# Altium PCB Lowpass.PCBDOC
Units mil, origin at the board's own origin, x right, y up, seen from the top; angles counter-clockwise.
Board outline 6000 x 4000 mil, 2 copper layers (Top Layer, Bottom Layer); 8 components, 7 nets, 22 pads, 0 vias.
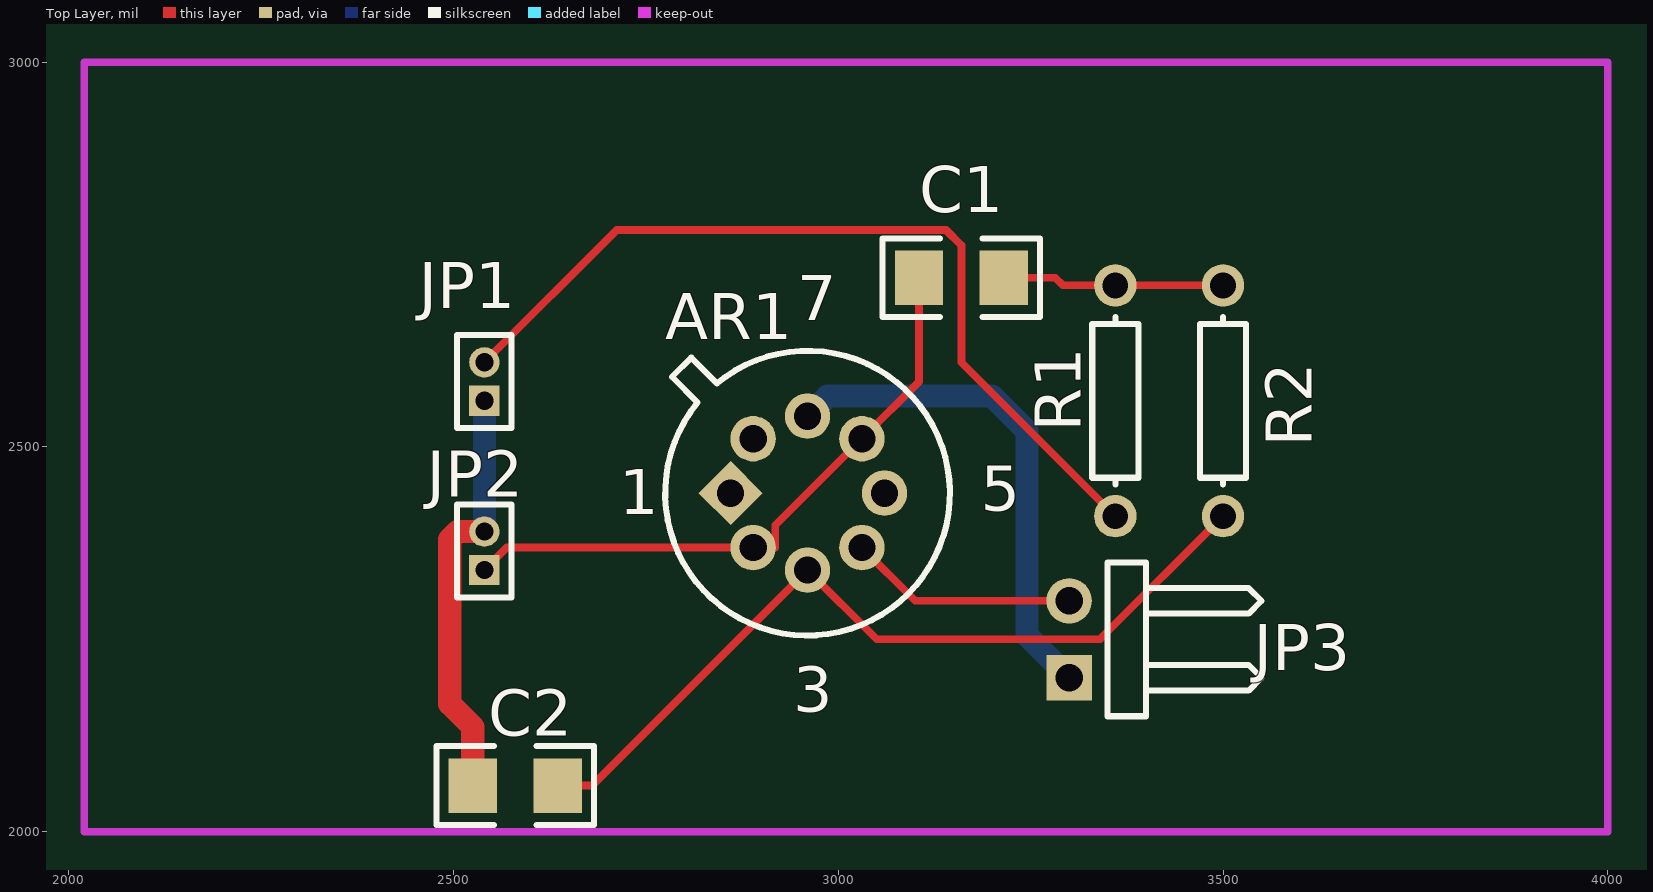
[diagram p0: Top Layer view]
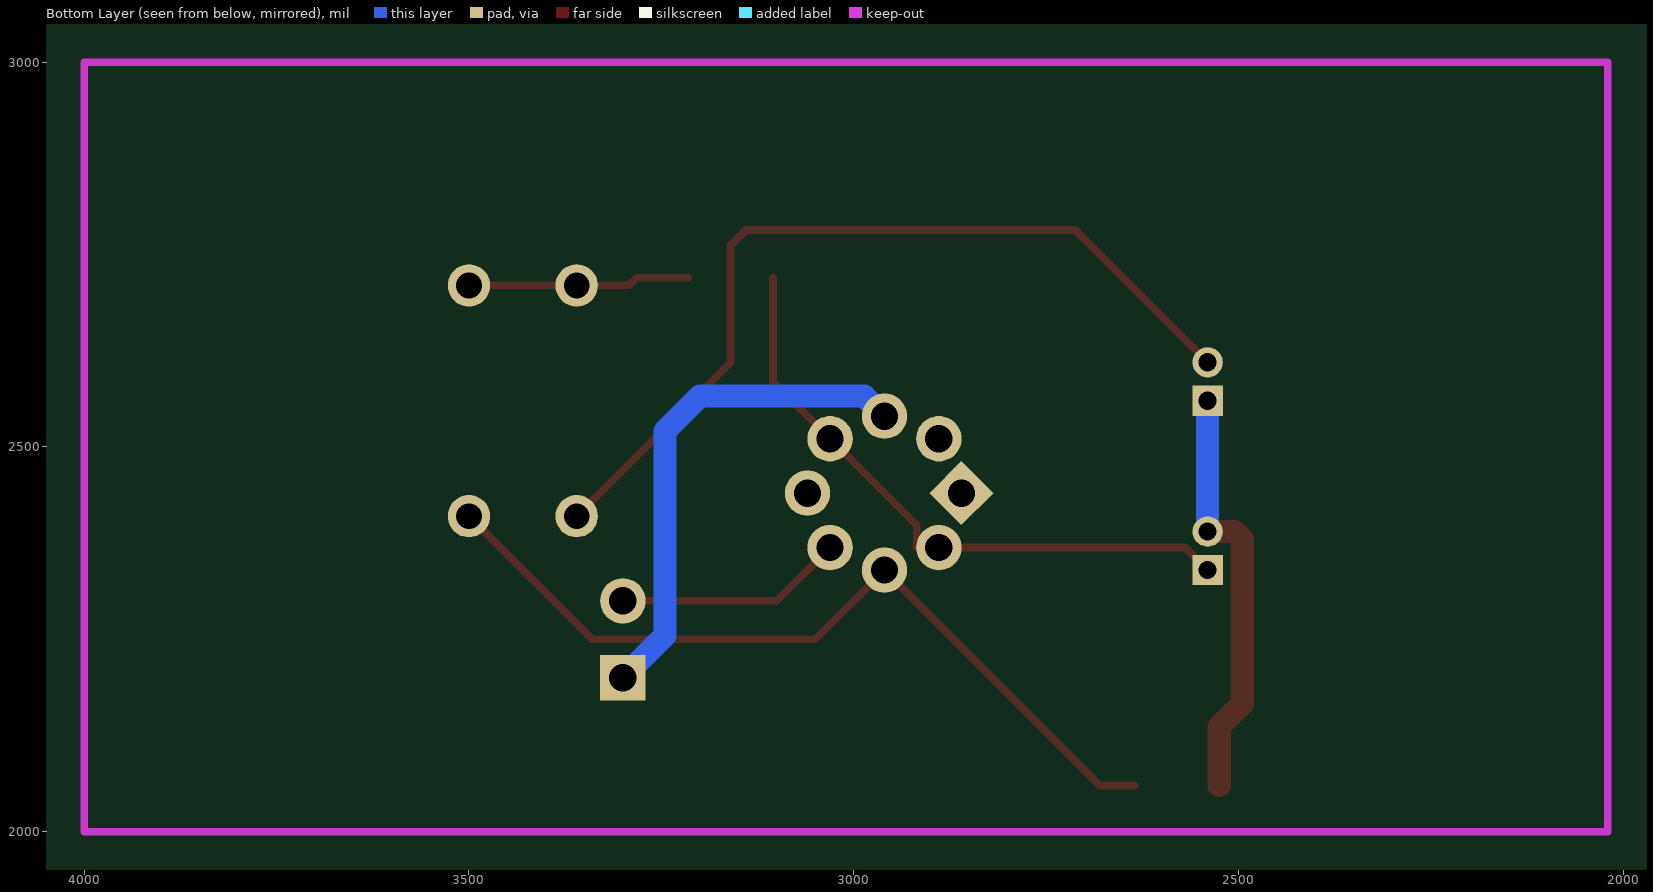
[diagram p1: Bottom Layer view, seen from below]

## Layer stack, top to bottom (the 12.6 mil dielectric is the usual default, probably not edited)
Top Layer: signal copper 1.4
Dielectric: dielectric 12.6, FR-4, Dk 4.8
Bottom Layer: signal copper 1.4

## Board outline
1000,1000 7000,1000 7000,5000 1000,5000

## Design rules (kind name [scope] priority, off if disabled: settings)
Clearance [All] p1: gap=10
ComponentClearance [All] p1: gap=10 collisioncheckmode=0
PolygonConnect [All] p1: connectstyle=Relief reliefconductorwidth=10 reliefentries=4 polygonreliefangle="90 Angle"
RoutingLayers [All] p1: top layer=Horizontal bottom layer=Vertical
RoutingTopology RoutingTopology_1 [(InNet(''))] p1: topology=Shortest
RoutingTopology [All] p2: topology=Shortest
RoutingVias [All] p1: holewidth=28 width=50 viastyle="Through Hole" minholewidth=28 minwidth=50 maxholewidth=28 maxwidth=50
SolderMaskExpansion [All] p1: expansion=4
TestPointUsage [All] p1: valid=0 allowmultiple=FALSE
Testpoint [All] p1: side=15 testpointundercomponent=TRUE minsize=40 maxsize=100 preferedsize=60 minholesize=0 maxholesize=40 preferedholesize=32 testpointgrid=1 style=1023 order=1234567890
Width Width_2 [InNet('GND')] p1: maxlimit=50 minlimit=20 preferedwidth=30
Width Width_1 [InNet('-VCC')] p2: maxlimit=50 minlimit=20 preferedwidth=30
Width [All] p3: maxlimit=10 minlimit=10 preferedwidth=10
15 further rules are at their usual default settings.

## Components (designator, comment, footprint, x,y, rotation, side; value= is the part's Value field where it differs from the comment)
AR1 "Op Amp" CAN-8/D9.4 2960,2440 r0 top
C1 "0.02μF" C3216-1206 3160,2720 r180 top
C2 "Cap Semi" C3216-1206 2580,2060 r0 top
JP1 "MHDR1X2" MHDR1X2 2540,2560 r90 top
JP2 "MHDR1X2" MHDR1X2 2540,2340 r90 top
JP3 "Header 2H" HDR1X2H 3300,2200 r90 top
R1 "Res1" AXIAL-0.3 3360,2560 r90 top
R2 "Res1" AXIAL-0.3 3500,2560 r270 top

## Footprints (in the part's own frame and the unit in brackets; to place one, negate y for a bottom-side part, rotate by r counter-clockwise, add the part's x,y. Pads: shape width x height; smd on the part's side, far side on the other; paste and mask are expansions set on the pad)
AXIAL-0.3 [mm]
  round 1.4 hole 0.85: 1(-3.81,0) 2(3.81,0)
  silkscreen extent -2.77,-0.76 2.77,0.76
C3216-1206 [mm]
  rect 1.6x1.8 smd: 1(-1.4,0) 2(1.4,0)
  silkscreen extent -2.6,-1.3 2.6,1.3
CAN-8/D9.4 [mm]
  rect 1.5x1.5 hole 0.9 rot 45: 1(-2.54,0)
  round 1.5 hole 0.9: 2(-1.796,-1.796) 3(0,-2.54) 4(1.796,-1.796) 5(2.54,0) 6(1.796,1.796) 7(0,2.54) 8(-1.796,1.796)
  silkscreen extent -4.7,-4.7 4.7,4.7
HDR1X2H [mm]
  rect 1.5x1.5 hole 0.9: 1(0,0)
  round 1.5 hole 0.9: 2(2.54,0)
  silkscreen extent -1.27,-6.35 3.81,-1.27
MHDR1X2 [mm]
  rect 1x1 hole 0.6: 1(0,0)
  round 1 hole 0.6: 2(1.27,0)
  silkscreen extent -0.9,-0.9 2.17,0.9

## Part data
AR1: "FET Operational Amplifier"
C1: library part "Cap Semi", "Capacitor (Semiconductor SIM Model)"
C2: "Capacitor (Semiconductor SIM Model)"
JP1 JP2: "Header, 2-Pin"
JP3: "Header, 2-Pin,  Right Angle"
R1 R2: "Resistor"

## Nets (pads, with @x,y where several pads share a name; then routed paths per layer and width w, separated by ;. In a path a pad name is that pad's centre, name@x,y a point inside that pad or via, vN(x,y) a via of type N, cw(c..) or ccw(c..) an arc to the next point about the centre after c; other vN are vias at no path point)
-VCC: AR1.7 JP3.1 | length 658.2
  Bottom Layer w30: AR1.7 2986,2566 3200,2566 3245,2521 3245,2255 JP3.1
GND: C2.1 JP1.1 JP2.2 | length 551.5
  Top Layer w30: C2.1 2524.88,2136.12 2495,2166 2495,2380 2505,2390 JP2.2
  Bottom Layer w30: JP2.2 JP1.1
NetAR1_2: AR1.2 AR1.6 C1.2 JP2.1 | length 818.3
  Top Layer w10: JP2.1 2569.29,2369.29 AR1.2 2918,2369.29 2918,2398 AR1.6 3104.88,2584.88 C1.2
NetAR1_3: AR1.3 C2.2 R2.2 | length 1084.4
  Top Layer w10: C2.2 2680,2060 AR1.3 3050,2250 3340,2250 R2.2
NetC1_1: C1.1 R1.2 R2.1 | length 289
  Top Layer w10: C1.1 3282,2720 3292,2710 R1.2 R2.1
NetJP1_2: JP1.2 R1.1 | length 1134.4
  Top Layer w10: JP1.2 2712,2782 3140,2782 3160,2762 3160,2610 R1.1
VCC: AR1.4 JP3.2 | length 298
  Top Layer w10: AR1.4 3100,2300 JP3.2
pads on no net: AR1.1 AR1.5 AR1.8

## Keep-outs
Keep-Out Layer:
  lines w10: 2020,2000 4000,2000 4000,3000 2020,3000 2020,2000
